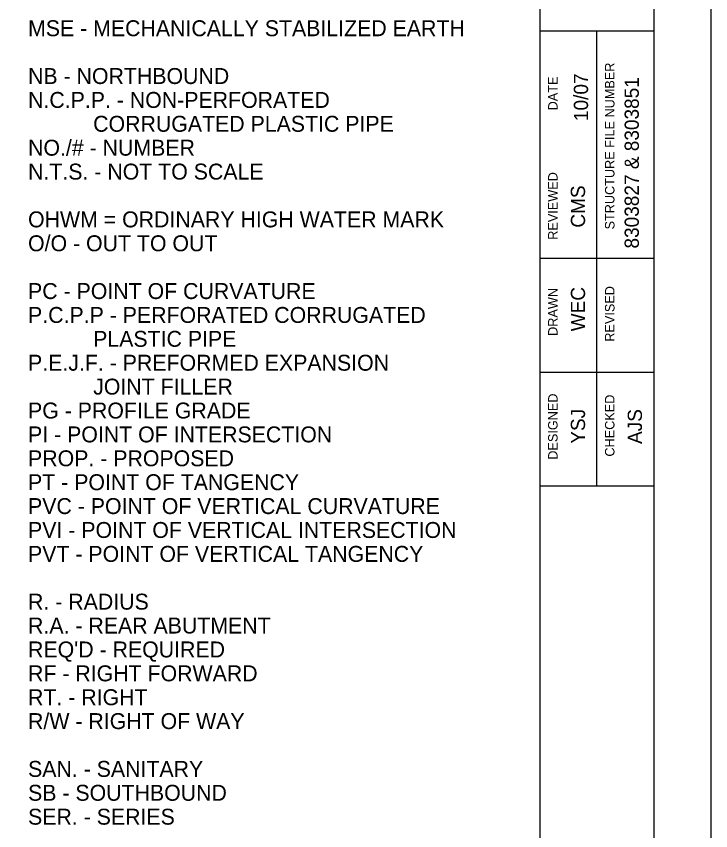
# Model space of a CAD drawing. Extents: x 0 to 34, y 0 to 22.
# Drawn here: x 27.9 to 34, y 10.97 to 18.13 of the extents above; entities that cross this region are included whole.
import ezdxf

# ---------------------------------------------------------------- set-up
doc = ezdxf.new("R2010")
doc.units = 0
for name, color, linetype in [('SH_Border', 7, 'Continuous'), ('SH_Cut_Line', 7, 'Continuous'), ('SH_Data', 7, 'Continuous')]:
    doc.layers.add(name, color=color, linetype=linetype)

msp = doc.modelspace()

# ---------------------------------------------------------------- linework, layer by layer
at = {"layer": 'SH_Border'}
for p, q in [((32.5, 0.5), (32.5, 21.5)), ((32.5, 0.5), (32.5, 21.5)), ((32.5, 0.5), (32.5, 21.5)), ((32.5, 18), (33.5, 18)), ((32.5, 18), (33.5, 18)), ((32.5, 18), (33.5, 18)), ((33, 14), (33, 18)), ((33, 14), (33, 18)), ((33, 14), (33, 18)), ((32.5, 16), (33.5, 16)), ((32.5, 16), (33.5, 16)), ((32.5, 16), (33.5, 16)), ((32.5, 15), (33.5, 15)), ((32.5, 15), (33.5, 15)), ((32.5, 15), (33.5, 15)), ((32.5, 14), (33.5, 14)), ((32.5, 14), (33.5, 14)), ((32.5, 14), (33.5, 14))]:
    msp.add_line(p, q, dxfattribs=at)
msp.add_lwpolyline([(2, 21.5), (33.5, 21.5), (33.5, 0.5), (2, 0.5)], close=True, dxfattribs=at)
at = {"layer": 'SH_Cut_Line'}
msp.add_lwpolyline([(0, 22), (34, 22), (34, 0), (0, 0)], close=True, dxfattribs=at)

# ---------------------------------------------------------------- texts
at = {"layer": 'SH_Data'}
for s, p in [('MSE - MECHANICALLY STABILIZED EARTH', (28.0004, 17.9516)), ('NB - NORTHBOUND', (28.0004, 17.5316)), ('N.C.P.P. - NON-PERFORATED', (28.0004, 17.3216)), ('           CORRUGATED PLASTIC PIPE', (28.0004, 17.1116)), ('NO./# - NUMBER', (28.0004, 16.9016)), ('N.T.S. - NOT TO SCALE', (28.0004, 16.6916)), ('OHWM = ORDINARY HIGH WATER MARK', (28.0004, 16.2716)), ('O/O - OUT TO OUT', (28.0004, 16.0616)), ('PC - POINT OF CURVATURE', (28.0004, 15.6416)), ('P.C.P.P - PERFORATED CORRUGATED', (28.0004, 15.4316)), ('           PLASTIC PIPE', (28.0004, 15.2216)), ('P.E.J.F. - PREFORMED EXPANSION', (28.0004, 15.0116)), ('           JOINT FILLER', (28.0004, 14.8016)), ('PG - PROFILE GRADE', (28.0004, 14.5916)), ('PI - POINT OF INTERSECTION', (28.0004, 14.3816)), ('PROP. - PROPOSED', (28.0004, 14.1716)), ('PT - POINT OF TANGENCY', (28.0004, 13.9616)), ('PVC - POINT OF VERTICAL CURVATURE', (28.0004, 13.7516)), ('PVI - POINT OF VERTICAL INTERSECTION', (28.0004, 13.5416)), ('PVT - POINT OF VERTICAL TANGENCY', (28.0004, 13.3316)), ('R. - RADIUS', (28.0004, 12.9116)), ('R.A. - REAR ABUTMENT', (28.0004, 12.7016)), ("REQ'D - REQUIRED", (28.0004, 12.4916)), ('RF - RIGHT FORWARD', (28.0004, 12.2816)), ('RT. - RIGHT', (28.0004, 12.0716)), ('R/W - RIGHT OF WAY', (28.0004, 11.8616)), ('SAN. - SANITARY', (28.0004, 11.4416)), ('SB - SOUTHBOUND', (28.0004, 11.2316)), ('SER. - SERIES', (28.0004, 11.0216))]:
    msp.add_text(s, height=0.14, dxfattribs=at).set_placement(p)
for s, height, p in [('STRUCTURE FILE NUMBER', 0.0833, (33.1542, 16.253)), ('10/07', 0.125, (32.9221, 17.206)), ('DATE', 0.0833, (32.6542, 17.2997)), ('8303827 & 8303851', 0.125, (33.3684, 16.0856)), ('REVIEWED', 0.0833, (32.6542, 16.1627)), ('CMS', 0.125, (32.8958, 16.2687)), ('REVISED', 0.0833, (33.1542, 15.2665)), ('DRAWN', 0.0833, (32.6542, 15.3177)), ('WEC', 0.125, (32.8958, 15.3576)), ('DESIGNED', 0.0833, (32.6542, 14.2292)), ('CHECKED', 0.0833, (33.1542, 14.2567)), ('YSJ', 0.125, (32.8958, 14.3699)), ('AJS', 0.125, (33.3958, 14.3675))]:
    msp.add_text(s, height=height, rotation=90, dxfattribs=at).set_placement(p)

doc.saveas('drawing.dxf')
